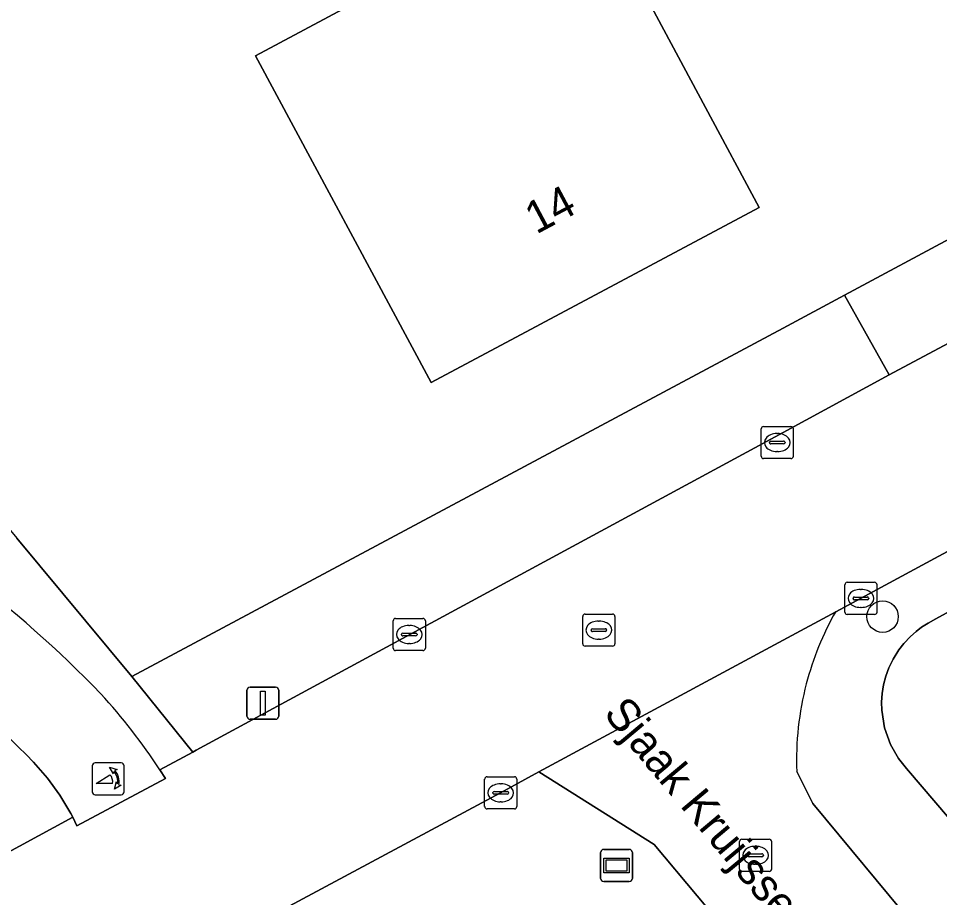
# Model space of a CAD drawing. Extents: x 157320 to 158835, y 386650 to 388491.
# Drawn here: x 157976.21 to 158004.87, y 387061.67 to 387089.01 of the extents above; entities that cross this region are included whole.
import ezdxf

# ---------------------------------------------------------------- set-up
doc = ezdxf.new("R2010")
doc.units = 0
for name, color, linetype in [('IMGEO_Boom', 7, 'Continuous'), ('IMGEO_Erf', 7, 'Continuous'), ('IMGEO_Fietspad_gesloten', 7, 'Continuous'), ('IMGEO_Groenvoorziening', 7, 'Continuous'), ('IMGEO_Hek', 7, 'Continuous'), ('IMGEO_Kolk', 7, 'Continuous'), ('IMGEO_Lichtmast', 7, 'Continuous'), ('IMGEO_Openbare_ruimte_label', 7, 'Continuous'), ('IMGEO_Pand', 7, 'Continuous'), ('IMGEO_Pand_nummerreeks', 7, 'Continuous'), ('IMGEO_Poller', 7, 'Continuous'), ('IMGEO_Rijbaan_lokaal_gesloten', 7, 'Continuous'), ('IMGEO_Rijbaan_lokaal_open', 7, 'Continuous'), ('IMGEO_Rioolput', 7, 'Continuous'), ('IMGEO_Straatnaambord', 7, 'Continuous'), ('IMGEO_Voetpad_halfverhard', 7, 'Continuous'), ('IMGEO_Voetpad_open', 7, 'Continuous')]:
    doc.layers.add(name, color=color, linetype=linetype)

msp = doc.modelspace()

# ---------------------------------------------------------------- linework, layer by layer
at = {"layer": 'IMGEO_Boom'}
msp.add_circle((158003.095, 387070.405), 0.489, dxfattribs=at)
at = {"layer": 'IMGEO_Erf'}
for points in [[(158037.112, 387136.881), (157958.343, 387094.408), (157976.161, 387072.845), (157979.736, 387068.538), (158000, 387079.38), (158001.909, 387080.4), (158005.465, 387082.305), (158007.056, 387083.156), (158008.759, 387084.067), (158026.431, 387093.464), (158029.806, 387095.432), (158030.803, 387095.859), (158041.408, 387101.597)], [(158047.047, 387093.46), (158025.644, 387081.721), (158021.209, 387079.347), (158004.755, 387070.333), (158004.513, 387070.205), (158004.307, 387070.073), (158004.138, 387069.944), (158003.959, 387069.785), (158003.759, 387069.571), (158003.603, 387069.369), (158003.425, 387069.084), (158003.294, 387068.813), (158003.2, 387068.555), (158003.128, 387068.28), (158003.085, 387068.018), (158003.066, 387067.749), (158003.071, 387067.494), (158003.157, 387066.946), (158003.343, 387066.428), (158003.592, 387065.998), (158003.842, 387065.687), (158012.355, 387055.717)]]:
    msp.add_lwpolyline(points, dxfattribs=at)
msp.add_lwpolyline([(157998.486, 387096.905), (157994.017, 387094.513), (157994.489, 387093.632), (157994.157, 387092.646), (157997.588, 387086.237), (157999.255, 387083.124), (157989.056, 387077.686), (157983.584, 387087.847), (157988.733, 387090.6), (157982.822, 387101.657), (157993.023, 387107.108)], close=True, dxfattribs=at)
at = {"layer": 'IMGEO_Fietspad_gesloten'}
msp.add_lwpolyline([(157975.97, 387066.58), (157976.209, 387066.35), (157976.446, 387066.118), (157976.683, 387065.88), (157977.116, 387065.382), (157977.503, 387064.848), (157977.841, 387064.281), (157977.902, 387064.165), (157977.968, 387064.034), (157978.031, 387063.902), (157980.781, 387065.373), (157980.61, 387065.638)], dxfattribs=at)
for centre, radius, start, end in [((157953.417, 387043.554), 35.227, 43.9597, 62.4864), ((157964.903, 387055.367), 18.767, 33.1818, 42.3401)]:
    msp.add_arc(centre, radius, start, end, dxfattribs=at)
at = {"layer": 'IMGEO_Groenvoorziening'}
for points in [[(158012.355, 387055.717), (158003.842, 387065.687), (158003.592, 387065.998), (158003.343, 387066.428), (158003.157, 387066.946), (158003.071, 387067.494), (158003.066, 387067.749), (158003.085, 387068.018), (158003.128, 387068.28), (158003.2, 387068.555), (158003.294, 387068.813), (158003.425, 387069.084), (158003.603, 387069.369), (158003.759, 387069.571), (158003.959, 387069.785), (158004.138, 387069.944), (158004.307, 387070.073), (158004.513, 387070.205), (158004.755, 387070.333), (158021.209, 387079.347), (158020.488, 387080.731), (158001.636, 387070.559)], [(157971.339, 387060.631), (157974.572, 387062.367), (157977.902, 387064.165), (157977.841, 387064.281), (157977.503, 387064.848), (157977.116, 387065.382), (157976.683, 387065.88), (157976.446, 387066.118), (157976.209, 387066.35), (157975.97, 387066.58)], [(158000, 387058.528), (157995.987, 387063.319), (157992.396, 387065.574), (157991.21, 387064.929), (157983.496, 387060.784)], [(158000.426, 387065.585), (158000.925, 387064.597), (158004.106, 387060.756)]]:
    msp.add_lwpolyline(points, dxfattribs=at)
msp.add_lwpolyline([(157981.633, 387066.187), (157981.742, 387066.255), (158000, 387076.136), (158003.296, 387077.92), (158001.909, 387080.4), (158000, 387079.38), (157979.736, 387068.538)], close=True, dxfattribs=at)
for centre, radius, start, end in [((158009.716, 387065.963), 9.296, 150.3671, 165.336), ((158009.704, 387065.958), 9.286, 165.2871, 182.2997)]:
    msp.add_arc(centre, radius, start, end, dxfattribs=at)
at = {"layer": 'IMGEO_Hek'}
for points in [[(158000, 387079.38), (158001.909, 387080.4)], [(157979.736, 387068.538), (158000, 387079.38)]]:
    msp.add_lwpolyline(points, dxfattribs=at)
at = {"layer": 'IMGEO_Kolk'}
for p, q in [((157999.317, 387075.392), (157999.317, 387076.244)), ((157999.392, 387076.318), (158000.244, 387076.318)), ((158000.318, 387076.244), (158000.318, 387075.392)), ((157999.619, 387075.861), (158000.017, 387075.861)), ((157999.805, 387076.098), (157999.83, 387076.098)), ((157999.576, 387075.812), (157999.576, 387075.824)), ((158000.014, 387075.775), (157999.616, 387075.775)), ((158000.06, 387075.824), (158000.06, 387075.812)), ((158000.244, 387075.318), (157999.392, 387075.318)), ((157999.828, 387075.538), (157999.803, 387075.538)), ((158001.92, 387070.546), (158001.92, 387071.398)), ((158001.995, 387071.472), (158002.847, 387071.472)), ((158002.921, 387071.398), (158002.921, 387070.546)), ((158002.179, 387070.966), (158002.179, 387070.978)), ((158002.222, 387071.015), (158002.62, 387071.015)), ((158002.408, 387071.252), (158002.433, 387071.252)), ((158002.663, 387070.978), (158002.663, 387070.966)), ((158002.617, 387070.929), (158002.219, 387070.929)), ((158002.431, 387070.692), (158002.406, 387070.692)), ((158002.847, 387070.472), (158001.995, 387070.472)), ((157987.869, 387069.423), (157987.869, 387070.275)), ((157987.944, 387070.349), (157988.796, 387070.349)), ((157988.357, 387070.129), (157988.382, 387070.129)), ((157988.87, 387070.275), (157988.87, 387069.423)), ((157988.128, 387069.843), (157988.128, 387069.855)), ((157988.171, 387069.892), (157988.569, 387069.892)), ((157988.612, 387069.855), (157988.612, 387069.843)), ((157988.566, 387069.806), (157988.168, 387069.806)), ((157988.38, 387069.569), (157988.355, 387069.569)), ((157988.796, 387069.349), (157987.944, 387069.349)), ((157990.715, 387064.499), (157990.715, 387065.351)), ((157990.79, 387065.425), (157991.642, 387065.425)), ((157991.716, 387065.351), (157991.716, 387064.499)), ((157991.017, 387064.968), (157991.415, 387064.968)), ((157991.203, 387065.205), (157991.228, 387065.205)), ((157990.974, 387064.919), (157990.974, 387064.931)), ((157991.412, 387064.882), (157991.014, 387064.882)), ((157991.458, 387064.931), (157991.458, 387064.919)), ((157991.642, 387064.425), (157990.79, 387064.425)), ((157991.226, 387064.645), (157991.201, 387064.645)), ((157998.643, 387062.556), (157998.643, 387063.408)), ((157998.718, 387063.482), (157999.57, 387063.482)), ((157999.131, 387063.262), (157999.156, 387063.262)), ((157999.644, 387063.408), (157999.644, 387062.556)), ((157998.902, 387062.976), (157998.902, 387062.988)), ((157998.945, 387063.025), (157999.343, 387063.025)), ((157999.386, 387062.988), (157999.386, 387062.976)), ((157999.34, 387062.939), (157998.942, 387062.939)), ((157999.154, 387062.702), (157999.129, 387062.702)), ((157999.57, 387062.482), (157998.718, 387062.482))]:
    msp.add_line(p, q, dxfattribs=at)
for points in [[(157999.317, 387075.392), (157999.317, 387076.244)], [(157999.392, 387076.318), (158000.244, 387076.318)], [(158000.318, 387076.244), (158000.318, 387075.392)], [(158000.244, 387075.318), (157999.392, 387075.318)], [(158001.92, 387070.546), (158001.92, 387071.398)], [(158001.995, 387071.472), (158002.847, 387071.472)], [(158002.921, 387071.398), (158002.921, 387070.546)], [(158002.847, 387070.472), (158001.995, 387070.472)], [(157987.869, 387069.423), (157987.869, 387070.275)], [(157987.944, 387070.349), (157988.796, 387070.349)], [(157988.87, 387070.275), (157988.87, 387069.423)], [(157988.796, 387069.349), (157987.944, 387069.349)], [(157990.715, 387064.499), (157990.715, 387065.351)], [(157990.79, 387065.425), (157991.642, 387065.425)], [(157991.716, 387065.351), (157991.716, 387064.499)], [(157991.642, 387064.425), (157990.79, 387064.425)], [(157998.643, 387062.556), (157998.643, 387063.408)], [(157998.718, 387063.482), (157999.57, 387063.482)], [(157999.644, 387063.408), (157999.644, 387062.556)], [(157999.57, 387062.482), (157998.718, 387062.482)]]:
    msp.add_lwpolyline(points, dxfattribs=at)
for centre, radius, start, end in [((157999.394, 387076.242), 0.0765, 91.552, 178.448), ((157999.394, 387076.242), 0.0765, 91.552, 178.448), ((158000.242, 387076.242), 0.0765, 1.552, 88.448), ((158000.242, 387076.242), 0.0765, 1.552, 88.448), ((157999.616, 387075.821), 0.0403, 85.8775, 175.7526), ((158000.021, 387075.823), 0.0386, 1.7309, 96.639), ((157999.613, 387075.811), 0.0366, 178.938, 274.7102), ((158000.017, 387075.818), 0.043, 264.8664, 352.4533), ((157999.394, 387075.394), 0.0765, 181.552, 268.448), ((157999.394, 387075.394), 0.0765, 181.552, 268.448), ((158000.242, 387075.394), 0.0765, 271.552, 358.448), ((158000.242, 387075.394), 0.0765, 271.552, 358.448), ((158001.997, 387071.396), 0.0765, 91.552, 178.448), ((158001.997, 387071.396), 0.0765, 91.552, 178.448), ((158002.845, 387071.396), 0.0765, 1.552, 88.448), ((158002.845, 387071.396), 0.0765, 1.552, 88.448), ((158002.219, 387070.975), 0.0403, 85.8775, 175.7526), ((158002.624, 387070.977), 0.0386, 1.7309, 96.639), ((158002.216, 387070.965), 0.0366, 178.938, 274.7102), ((158002.62, 387070.972), 0.043, 264.8664, 352.4533), ((158001.997, 387070.548), 0.0765, 181.552, 268.448), ((158001.997, 387070.548), 0.0765, 181.552, 268.448), ((158002.845, 387070.548), 0.0765, 271.552, 358.448), ((158002.845, 387070.548), 0.0765, 271.552, 358.448), ((157987.946, 387070.273), 0.0765, 91.552, 178.448), ((157987.946, 387070.273), 0.0765, 91.552, 178.448), ((157988.794, 387070.273), 0.0765, 1.552, 88.448), ((157988.794, 387070.273), 0.0765, 1.552, 88.448), ((157988.168, 387069.852), 0.0403, 85.8775, 175.7526), ((157988.165, 387069.842), 0.0366, 178.938, 274.7102), ((157988.569, 387069.849), 0.043, 264.8664, 352.4533), ((157988.573, 387069.854), 0.0386, 1.7309, 96.639), ((157987.946, 387069.425), 0.0765, 181.552, 268.448), ((157987.946, 387069.425), 0.0765, 181.552, 268.448), ((157988.794, 387069.425), 0.0765, 271.552, 358.448), ((157988.794, 387069.425), 0.0765, 271.552, 358.448), ((157990.792, 387065.349), 0.0765, 91.552, 178.448), ((157990.792, 387065.349), 0.0765, 91.552, 178.448), ((157991.64, 387065.349), 0.0765, 1.552, 88.448), ((157991.64, 387065.349), 0.0765, 1.552, 88.448), ((157991.014, 387064.928), 0.0403, 85.8775, 175.7526), ((157991.419, 387064.93), 0.0386, 1.7309, 96.639), ((157991.011, 387064.918), 0.0366, 178.938, 274.7102), ((157991.415, 387064.925), 0.043, 264.8664, 352.4533), ((157990.792, 387064.501), 0.0765, 181.552, 268.448), ((157990.792, 387064.501), 0.0765, 181.552, 268.448), ((157991.64, 387064.501), 0.0765, 271.552, 358.448), ((157991.64, 387064.501), 0.0765, 271.552, 358.448), ((157998.72, 387063.406), 0.0765, 91.552, 178.448), ((157998.72, 387063.406), 0.0765, 91.552, 178.448), ((157999.568, 387063.406), 0.0765, 1.552, 88.448), ((157999.568, 387063.406), 0.0765, 1.552, 88.448), ((157998.942, 387062.985), 0.0403, 85.8775, 175.7526), ((157998.939, 387062.975), 0.0366, 178.938, 274.7102), ((157999.343, 387062.982), 0.043, 264.8664, 352.4533), ((157999.347, 387062.987), 0.0386, 1.7309, 96.639), ((157998.72, 387062.558), 0.0765, 181.552, 268.448), ((157998.72, 387062.558), 0.0765, 181.552, 268.448), ((157999.568, 387062.558), 0.0765, 271.552, 358.448), ((157999.568, 387062.558), 0.0765, 271.552, 358.448)]:
    msp.add_arc(centre, radius, start, end, dxfattribs=at)
for centre, major_axis, ratio, start_param, end_param in [((157999.804, 387075.818), (-0.387, 0.002), 0.722429, 4.712389, 7.853982), ((157999.829, 387075.818), (-0.39, 0.002), 0.717154, 1.570796, 4.712389), ((158002.407, 387070.972), (-0.387, 0.002), 0.722429, 4.712389, 7.853982), ((158002.432, 387070.972), (-0.39, 0.002), 0.717154, 1.570796, 4.712389), ((157988.356, 387069.849), (-0.387, 0.002), 0.722429, 4.712389, 7.853982), ((157988.381, 387069.849), (-0.39, 0.002), 0.717154, 1.570796, 4.712389), ((157991.202, 387064.925), (-0.387, 0.002), 0.722429, 4.712389, 7.853982), ((157991.227, 387064.925), (-0.39, 0.002), 0.717154, 1.570796, 4.712389), ((157999.13, 387062.982), (-0.387, 0.002), 0.722429, 4.712389, 7.853982), ((157999.155, 387062.982), (-0.39, 0.002), 0.717154, 1.570796, 4.712389)]:
    msp.add_ellipse(centre, major_axis=major_axis, ratio=ratio, start_param=start_param, end_param=end_param, dxfattribs=at)
at = {"layer": 'IMGEO_Lichtmast'}
for p, q in [((157983.317, 387067.313), (157983.317, 387068.113)), ((157983.317, 387068.113), (157983.317, 387067.313)), ((157983.417, 387068.213), (157984.207, 387068.213)), ((157984.207, 387068.213), (157983.417, 387068.213)), ((157984.307, 387068.113), (157984.307, 387067.313)), ((157984.307, 387067.313), (157984.307, 387068.113)), ((157984.207, 387067.213), (157983.417, 387067.213)), ((157983.417, 387067.213), (157984.207, 387067.213))]:
    msp.add_line(p, q, dxfattribs=at)
msp.add_lwpolyline([(157983.737, 387068.088), (157983.887, 387068.088), (157983.887, 387067.338), (157983.737, 387067.338), (157983.737, 387068.088)], dxfattribs=at)
for centre, start, end in [((157983.417, 387068.113), 90, 180), ((157983.417, 387068.113), 90, 180), ((157984.207, 387068.113), 0, 90), ((157984.207, 387068.113), 360, 90), ((157983.417, 387067.313), 180, 270), ((157983.417, 387067.313), 180, 270), ((157984.207, 387067.313), 270, 0), ((157984.207, 387067.313), 270, 0)]:
    msp.add_arc(centre, 0.1, start, end, dxfattribs=at)
at = {"layer": 'IMGEO_Pand'}
msp.add_lwpolyline([(157998.486, 387096.905), (157993.023, 387107.108), (157982.822, 387101.657), (157988.733, 387090.6), (157983.584, 387087.847), (157989.056, 387077.686), (157999.255, 387083.124), (157997.588, 387086.237), (157994.157, 387092.646), (157994.489, 387093.632), (157994.017, 387094.513)], close=True, dxfattribs=at)
at = {"layer": 'IMGEO_Poller'}
for p, q in [((157979.407, 387065.859), (157978.599, 387065.859)), ((157979.407, 387065.859), (157978.599, 387065.859)), ((157978.505, 387065.764), (157978.505, 387064.957)), ((157978.505, 387065.764), (157978.505, 387064.957)), ((157979.501, 387064.957), (157979.501, 387065.764)), ((157979.501, 387064.957), (157979.501, 387065.764)), ((157978.599, 387064.862), (157979.407, 387064.862)), ((157978.599, 387064.862), (157979.407, 387064.862))]:
    msp.add_line(p, q, dxfattribs=at)
for points in [[(157979.184, 387065.588), (157979.172, 387065.515), (157979.047, 387065.72)], [(157979.047, 387065.72), (157979.278, 387065.654), (157979.207, 387065.622)], [(157979.14, 387065.215), (157978.627, 387065.215), (157979.057, 387065.49)], [(157979.2, 387065.043), (157979.266, 387065.274), (157979.296, 387065.206)], [(157979.332, 387065.179), (157979.404, 387065.168), (157979.2, 387065.043)]]:
    msp.add_lwpolyline(points, dxfattribs=at)
for centre, radius, start, end in [((157978.599, 387065.764), 0.0946, 90, 180), ((157978.599, 387065.764), 0.0946, 90, 180), ((157979.407, 387065.764), 0.0946, 0, 90), ((157979.407, 387065.764), 0.0946, 0, 90), ((157978.826, 387065.275), 0.476, 351.7527, 41.1691), ((157978.826, 387065.275), 0.516, 349.3569, 42.2912), ((157978.812, 387065.265), 0.332, 351.3247, 42.4854), ((157978.599, 387064.957), 0.0946, 180, 270), ((157978.599, 387064.957), 0.0946, 180, 270), ((157979.407, 387064.957), 0.0946, 270, 0), ((157979.407, 387064.957), 0.0946, 270, 0)]:
    msp.add_arc(centre, radius, start, end, dxfattribs=at)
at = {"layer": 'IMGEO_Rijbaan_lokaal_gesloten'}
for points in [[(158069.112, 387113.407), (158053.278, 387104.849), (158048.471, 387102.262), (158043.652, 387099.663), (158042.727, 387099.157), (158031.216, 387092.927), (158027.751, 387091.073), (158006.853, 387079.818), (158003.296, 387077.92), (158000, 387076.136), (157981.742, 387066.255), (157981.633, 387066.187), (157980.61, 387065.638), (157980.781, 387065.373), (157978.031, 387063.902), (157977.968, 387064.034), (157977.902, 387064.165), (157974.572, 387062.367), (157971.339, 387060.631)], [(157968.704, 387058.691), (157973.431, 387055.39), (157978.256, 387057.971), (157980.806, 387059.335), (157980.664, 387059.588), (157983.342, 387061.057), (157983.496, 387060.784), (157991.21, 387064.929), (157992.396, 387065.574), (158000, 387069.676), (158001.636, 387070.559), (158020.488, 387080.731), (158024.905, 387083.087), (158046.373, 387094.699), (158049.829, 387096.568), (158051.968, 387097.719), (158061.394, 387102.79)]]:
    msp.add_lwpolyline(points, dxfattribs=at)
at = {"layer": 'IMGEO_Rijbaan_lokaal_open'}
for points in [[(158001.636, 387070.559), (158000, 387069.676), (157992.396, 387065.574), (157995.987, 387063.319), (158000, 387058.528)], [(158054.968, 387000), (158051.175, 387004.53), (158049.31, 387006.761), (158048.553, 387007.661), (158041.617, 387015.907), (158041.04, 387016.593), (158039.109, 387018.889), (158038.917, 387019.117), (158036.342, 387022.212), (158035.092, 387023.711), (158026.305, 387034.245), (158023.233, 387037.907), (158010.565, 387053.026), (158009.884, 387053.813), (158004.106, 387060.756), (158000.925, 387064.597), (158000.426, 387065.585)]]:
    msp.add_lwpolyline(points, dxfattribs=at)
for centre, radius, start, end in [((158009.716, 387065.963), 9.296, 150.3671, 165.336), ((158009.704, 387065.958), 9.286, 165.2871, 182.2997)]:
    msp.add_arc(centre, radius, start, end, dxfattribs=at)
at = {"layer": 'IMGEO_Rioolput'}
for p, q in [((157993.767, 387069.56), (157993.767, 387070.412)), ((157993.842, 387070.486), (157994.694, 387070.486)), ((157994.768, 387070.412), (157994.768, 387069.56)), ((157994.255, 387070.266), (157994.28, 387070.266)), ((157994.026, 387069.98), (157994.026, 387069.992)), ((157994.464, 387069.943), (157994.066, 387069.943)), ((157994.069, 387070.029), (157994.467, 387070.029)), ((157994.51, 387069.992), (157994.51, 387069.98)), ((157994.278, 387069.706), (157994.253, 387069.706)), ((157994.694, 387069.486), (157993.842, 387069.486))]:
    msp.add_line(p, q, dxfattribs=at)
for points in [[(157993.767, 387069.56), (157993.767, 387070.412)], [(157993.842, 387070.486), (157994.694, 387070.486)], [(157994.768, 387070.412), (157994.768, 387069.56)], [(157994.694, 387069.486), (157993.842, 387069.486)]]:
    msp.add_lwpolyline(points, dxfattribs=at)
for centre, radius, start, end in [((157993.844, 387070.41), 0.0765, 91.552, 178.448), ((157993.844, 387070.41), 0.0765, 91.552, 178.448), ((157994.692, 387070.41), 0.0765, 1.552, 88.448), ((157994.692, 387070.41), 0.0765, 1.552, 88.448), ((157994.066, 387069.989), 0.0403, 85.8775, 175.7526), ((157994.063, 387069.979), 0.0366, 178.938, 274.7102), ((157994.467, 387069.986), 0.043, 264.8664, 352.4533), ((157994.471, 387069.991), 0.0386, 1.7309, 96.639), ((157993.844, 387069.562), 0.0765, 181.552, 268.448), ((157993.844, 387069.562), 0.0765, 181.552, 268.448), ((157994.692, 387069.562), 0.0765, 271.552, 358.448), ((157994.692, 387069.562), 0.0765, 271.552, 358.448)]:
    msp.add_arc(centre, radius, start, end, dxfattribs=at)
for centre, major_axis, ratio, start_param, end_param in [((157994.254, 387069.986), (-0.387, 0.002), 0.722429, 4.712389, 7.853982), ((157994.279, 387069.986), (-0.39, 0.002), 0.717154, 1.570796, 4.712389)]:
    msp.add_ellipse(centre, major_axis=major_axis, ratio=ratio, start_param=start_param, end_param=end_param, dxfattribs=at)
at = {"layer": 'IMGEO_Straatnaambord'}
for p, q in [((157994.323, 387062.266), (157994.323, 387063.066)), ((157994.323, 387063.066), (157994.323, 387062.266)), ((157994.423, 387063.166), (157995.213, 387063.166)), ((157995.213, 387063.166), (157994.423, 387063.166)), ((157995.313, 387063.066), (157995.313, 387062.266)), ((157995.313, 387062.266), (157995.313, 387063.066)), ((157995.213, 387062.166), (157994.423, 387062.166)), ((157994.423, 387062.166), (157995.213, 387062.166))]:
    msp.add_line(p, q, dxfattribs=at)
for points in [[(157994.424, 387062.898), (157995.212, 387062.898), (157995.212, 387062.434), (157994.424, 387062.434), (157994.424, 387062.898)], [(157994.489, 387062.833), (157994.489, 387062.499), (157995.147, 387062.499), (157995.147, 387062.833), (157994.489, 387062.833)]]:
    msp.add_lwpolyline(points, dxfattribs=at)
for centre, start, end in [((157994.423, 387063.066), 90, 180), ((157994.423, 387063.066), 90, 180), ((157995.213, 387063.066), 0, 90), ((157995.213, 387063.066), 360, 90), ((157994.423, 387062.266), 180, 270), ((157994.423, 387062.266), 180, 270), ((157995.213, 387062.266), 270, 0), ((157995.213, 387062.266), 270, 0)]:
    msp.add_arc(centre, 0.1, start, end, dxfattribs=at)
at = {"layer": 'IMGEO_Voetpad_halfverhard'}
msp.add_lwpolyline([(157980.61, 387065.638), (157981.633, 387066.187), (157979.736, 387068.538), (157976.161, 387072.845)], dxfattribs=at)
for centre, radius, start, end in [((157953.417, 387043.554), 35.227, 43.9597, 62.4864), ((157964.903, 387055.367), 18.767, 33.1818, 42.3401)]:
    msp.add_arc(centre, radius, start, end, dxfattribs=at)
at = {"layer": 'IMGEO_Voetpad_open'}
msp.add_lwpolyline([(158006.159, 387081.061), (158007.729, 387081.907), (158007.056, 387083.156), (158005.465, 387082.305), (158001.909, 387080.4), (158003.296, 387077.92), (158006.853, 387079.818)], close=True, dxfattribs=at)

# ---------------------------------------------------------------- texts
at = {"layer": 'IMGEO_Openbare_ruimte_label'}
msp.add_text('Sjaak Kruijssenlaan', height=1, rotation=309.9303, dxfattribs=at).set_placement((157994.384, 387067.373))
at = {"layer": 'IMGEO_Pand_nummerreeks'}
msp.add_text('14', height=1, rotation=28.0635, dxfattribs=at).set_placement((157992.321, 387082.283))

doc.saveas('drawing.dxf')
